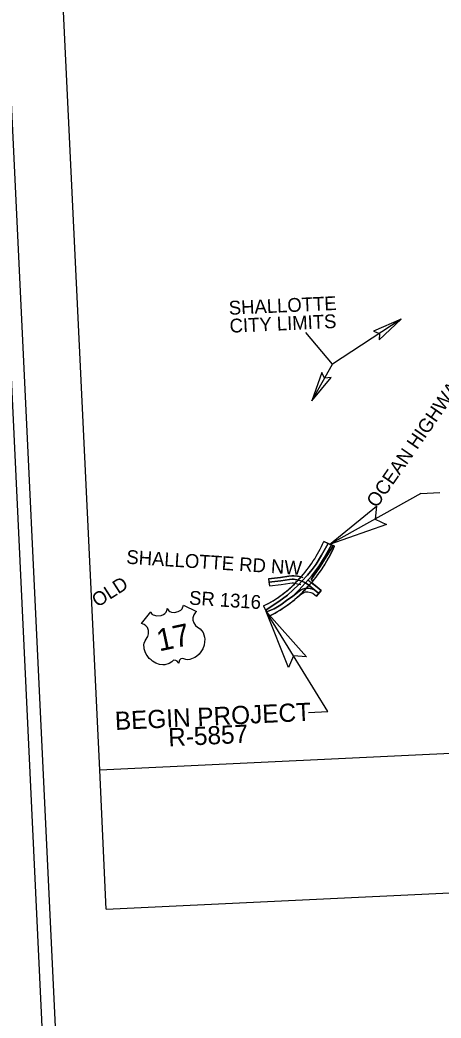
# Model space of a CAD drawing. Extents: x 2170913 to 2188101, y 74009 to 87693.
# Drawn here: x 2172605 to 2173761, y 78286 to 81028 of the extents above; entities that cross this region are included whole.
import ezdxf

# ---------------------------------------------------------------- set-up
doc = ezdxf.new("R2010")
doc.units = 0
for name, color, linetype in [('CTL Primary Horizontal and Vertical Cogo Elevation', 7, 'Continuous'), ('CTL Primary Horizontal Cogo Number', 7, 'Continuous'), ('Exist Other Culture Fence Line', 7, 'Continuous'), ('Exist Right of Way Monument CELL', 7, 'Continuous'), ('Exist Structure Minor Pipes RCP 15 Inch', 7, 'Continuous'), ('Exist Structure Minor Storm Sewer Manhole CELL', 7, 'Continuous'), ('Exist Utilities Water Fire Hydrant CELL', 7, 'Continuous')]:
    doc.layers.add(name, color=color, linetype=linetype)

msp = doc.modelspace()

# ---------------------------------------------------------------- linework, layer by layer
at = {"layer": 'CTL Primary Horizontal and Vertical Cogo Elevation'}
for p, q in [((2173651.6, 80206.1), (2173463, 80082.7)), ((2173463, 80082.7), (2173389.4, 80169.4)), ((2173406, 79981.3), (2173463, 80082.7)), ((2173705.6, 79727.3), (2173454.5, 79587.1)), ((2173705.6, 79727.3), (2173757.7, 79729.7)), ((2173449.6, 79128.3), (2173280.8, 79402.9)), ((2173396.8, 79125.7), (2173449.6, 79128.3)), ((2172841.7, 78585.3), (2172823.6, 78966.9)), ((2172841.7, 78585.3), (2175789.7, 78725.5))]:
    msp.add_line(p, q, dxfattribs=at)
msp.add_lwpolyline([(2172704.4, 81472.7), (2175652.3, 81612.9), (2175771.5, 79107.1), (2172823.6, 78966.9)], close=True, dxfattribs=at)
at = {"layer": 'CTL Primary Horizontal Cogo Number'}
for p, q in [((2172850.9, 74374.1), (2172499.4, 81766.8)), ((2172823.4, 75716.6), (2172535.6, 81768.5))]:
    msp.add_line(p, q, dxfattribs=at)
at = {"layer": 'Exist Other Culture Fence Line'}
msp.add_lwpolyline([(2172938, 79370.1), (2172963.9, 79401.6), (2172967.1, 79395.9), (2172969.9, 79393.8), (2172980, 79390.8), (2172991.9, 79392.1), (2172998.4, 79394.7), (2173002.5, 79397.5), (2173005.6, 79400.6), (2173008.8, 79408.5), (2173008.5, 79411.1), (2173013.1, 79404.3), (2173015.9, 79402.5), (2173021.1, 79400.8), (2173028.8, 79400.2), (2173039.3, 79402.5), (2173046.2, 79406.2), (2173050.2, 79410.1), (2173053.2, 79420.6), (2173089.6, 79402.4), (2173085.3, 79398.7), (2173081.7, 79393.5), (2173079.3, 79385), (2173079.4, 79379.1), (2173081.6, 79371.3), (2173086.3, 79364.3), (2173091.9, 79359.6), (2173099.3, 79354.9), (2173103.4, 79350.7), (2173107.3, 79344.8), (2173111.3, 79332.6), (2173111.9, 79327), (2173111.7, 79319.5), (2173110.1, 79310.2), (2173106.3, 79299.9), (2173101.6, 79291.9), (2173096.7, 79285.6), (2173089.6, 79279.1), (2173085.1, 79276.1), (2173071.2, 79270.8), (2173063.9, 79270.3), (2173060, 79270.7), (2173054.1, 79272.4), (2173051.9, 79273.2), (2173046.5, 79272.3), (2173042.9, 79268.7), (2173041.5, 79266.3), (2173040.4, 79260.7), (2173036.2, 79266), (2173032.9, 79268), (2173026.5, 79268.7), (2173022, 79264.5), (2173014.4, 79259.6), (2173002, 79256.3), (2172996.5, 79256.3), (2172987.6, 79257.6), (2172977.7, 79261), (2172968.5, 79266.5), (2172964.6, 79269.6), (2172959.8, 79274), (2172953.6, 79281.8), (2172951.5, 79285.2), (2172948.2, 79292.1), (2172946, 79299.9), (2172945.4, 79303.2), (2172944.3, 79310.9), (2172946, 79315.6), (2172948, 79322), (2172954.1, 79331.5), (2172955.7, 79334.5), (2172957.6, 79341), (2172957.3, 79350.8), (2172954.5, 79358.5), (2172950.6, 79363.5), (2172945.5, 79367.5), (2172938.5, 79370), (2172938, 79370.1), (2172963.9, 79401.6)], dxfattribs=at)
at = {"layer": 'Exist Right of Way Monument CELL'}
for p, q in [((2173450.5, 79590), (2173432.6, 79557.6)), ((2173450.5, 79590), (2173438.7, 79595.1)), ((2173455.4, 79587.9), (2173450.5, 79590)), ((2173459.6, 79586.1), (2173455.9, 79587.7)), ((2173464.9, 79583.8), (2173459.6, 79586.1)), ((2173462.9, 79580.1), (2173464.9, 79583.8)), ((2173468.1, 79582.4), (2173464.9, 79583.8)), ((2173432.6, 79557.6), (2173417.4, 79532.8)), ((2173427.3, 79523.4), (2173462.9, 79580.1)), ((2173405.4, 79500.1), (2173388.7, 79481.3)), ((2173404.5, 79490.8), (2173427.3, 79523.4)), ((2173287.2, 79492.9), (2173289.4, 79473.1)), ((2173287.2, 79492.9), (2173288.3, 79483)), ((2173288.3, 79483), (2173289.4, 79473.1)), ((2173388.7, 79481.3), (2173378.3, 79486.5)), ((2173378.3, 79486.5), (2173388.7, 79481.3)), ((2173388.7, 79481.3), (2173398.1, 79474.7)), ((2173398.1, 79474.7), (2173398.3, 79474.5)), ((2173413.9, 79461.4), (2173398.3, 79474.5)), ((2173398.3, 79474.5), (2173413.9, 79461.4)), ((2173408.9, 79486.6), (2173404.5, 79490.8)), ((2173404.5, 79490.8), (2173408.9, 79486.6)), ((2173315.4, 79429.8), (2173339.3, 79448.1)), ((2173371.3, 79462.4), (2173352.8, 79444.3)), ((2173413.9, 79461.4), (2173406, 79465)), ((2173408.6, 79452.8), (2173418.8, 79444.7)), ((2173431.3, 79460.3), (2173418.8, 79444.7)), ((2173418.8, 79444.7), (2173425.2, 79452.7)), ((2173425.2, 79452.7), (2173431.3, 79460.3)), ((2173273.5, 79418.3), (2173279.5, 79405.8)), ((2173320.9, 79421.3), (2173340.4, 79436)), ((2173340.4, 79436), (2173352.8, 79444.3)), ((2173279.5, 79405.8), (2173281.1, 79402.5)), ((2173281.1, 79402.5), (2173281.6, 79402)), ((2173281.6, 79402), (2173286, 79403.5)), ((2173281.6, 79402), (2173291.1, 79391.3))]:
    msp.add_line(p, q, dxfattribs=at)
for points in [[(2173378.3, 79486.5), (2173394.1, 79502.2), (2173406.6, 79517.9), (2173417.4, 79532.8), (2173432.6, 79557.6), (2173450.5, 79590)], [(2173388.7, 79481.3), (2173405.4, 79500.1), (2173425.2, 79526.7), (2173440.2, 79550.5), (2173459.6, 79586.1)], [(2173464.9, 79583.8), (2173462.9, 79580.1), (2173427.3, 79523.4), (2173404.5, 79490.8)], [(2173459.6, 79586.1), (2173440.2, 79550.5), (2173425.2, 79526.7), (2173405.4, 79500.1)], [(2173455.9, 79587.7), (2173454.5, 79587.1), (2173455.4, 79587.9)], [(2173417.4, 79532.8), (2173406.6, 79517.9), (2173394.1, 79502.2), (2173378.3, 79486.5)], [(2173287.2, 79492.9), (2173319.6, 79496.6), (2173343, 79500.2), (2173350.8, 79501.2), (2173356.7, 79501.2), (2173366.5, 79499.8), (2173375.5, 79497.6), (2173380.9, 79496.2)], [(2173375.9, 79497.5), (2173375.5, 79497.6), (2173366.5, 79499.8), (2173356.7, 79501.2), (2173350.8, 79501.2), (2173343, 79500.2), (2173319.6, 79496.6), (2173287.2, 79492.9)], [(2173378.3, 79486.5), (2173369, 79475.7), (2173355, 79462.1), (2173339.3, 79448.1), (2173315.4, 79429.8), (2173291.8, 79414.3), (2173280, 79406.2), (2173279.5, 79405.8)], [(2173368.3, 79489.1), (2173364.6, 79489.9), (2173356, 79491.2), (2173351.5, 79491.2), (2173344.4, 79490.3), (2173320.9, 79486.7), (2173288.3, 79483)], [(2173288.3, 79483), (2173320.9, 79486.7), (2173344.4, 79490.3)], [(2173289.4, 79473.1), (2173322.2, 79476.8), (2173345.8, 79480.4), (2173352.2, 79481.2), (2173355.2, 79481.2), (2173362.7, 79480.1), (2173370.6, 79478.2), (2173375.7, 79476.8)], [(2173289.4, 79473.1), (2173322.2, 79476.8), (2173345.8, 79480.4), (2173352.2, 79481.2), (2173355.2, 79481.2), (2173360.2, 79480.5)], [(2173339.3, 79448.1), (2173355, 79462.1), (2173369, 79475.7), (2173378.3, 79486.5)], [(2173344.4, 79490.3), (2173351.5, 79491.2), (2173356, 79491.2)], [(2173352.8, 79444.3), (2173371.3, 79462.4), (2173378.2, 79470.5), (2173388.7, 79481.3)], [(2173356, 79491.2), (2173364.6, 79489.9), (2173368.3, 79489.1)], [(2173378.3, 79486.5), (2173373, 79487.9), (2173368.3, 79489.1)], [(2173368.3, 79489.1), (2173373, 79487.9), (2173378.3, 79486.5)], [(2173388.7, 79481.3), (2173378.2, 79470.5), (2173371.3, 79462.4)], [(2173398.3, 79474.5), (2173398.1, 79474.7), (2173388.7, 79481.3)], [(2173394.5, 79489.5), (2173404.2, 79482.6), (2173420.2, 79469.2), (2173431.3, 79460.3)], [(2173431.3, 79460.3), (2173420.2, 79469.2), (2173404.9, 79482)], [(2173391.2, 79466.7), (2173386.5, 79466.4), (2173380.2, 79464.2), (2173374.4, 79461.1), (2173367.9, 79456.1), (2173352.8, 79444.3)], [(2173352.8, 79444.3), (2173367.9, 79456.1), (2173374.4, 79461.1), (2173380.2, 79464.2), (2173386.5, 79466.4), (2173391.2, 79466.7)], [(2173358.9, 79436.4), (2173374.1, 79448.2), (2173379.8, 79452.6), (2173384.2, 79455), (2173388.5, 79456.5), (2173391.7, 79456.7), (2173395.3, 79456.7), (2173403, 79455.3), (2173408.6, 79452.8)], [(2173366.5, 79442.3), (2173374.1, 79448.2), (2173379.8, 79452.6), (2173384.2, 79455), (2173388.5, 79456.5), (2173391.7, 79456.7), (2173395.3, 79456.7), (2173403, 79455.3), (2173408.6, 79452.8)], [(2173391.3, 79466.7), (2173391.2, 79466.7)], [(2173391.3, 79466.8), (2173391.3, 79466.7)], [(2173391.3, 79466.7), (2173396.2, 79466.7), (2173406, 79465), (2173413.9, 79461.4)], [(2173406, 79465), (2173396.2, 79466.7), (2173391.3, 79466.7)], [(2173408.6, 79452.8), (2173418.8, 79444.7)], [(2173425.2, 79452.7), (2173424.2, 79453.2), (2173413.9, 79461.4)], [(2173413.9, 79461.4), (2173424.2, 79453.2), (2173425.2, 79452.7)], [(2173279.5, 79405.8), (2173280, 79406.2), (2173291.8, 79414.3), (2173315.4, 79429.8)], [(2173352.8, 79444.3), (2173340.4, 79436), (2173320.9, 79421.3), (2173302.6, 79410.4), (2173286, 79403.5), (2173281.6, 79402)], [(2173286, 79403.5), (2173302.6, 79410.4), (2173320.9, 79421.3)]]:
    msp.add_lwpolyline(points, dxfattribs=at)
for centre, radius, start, end in [((2173115.2, 79734.2), 352.2, 316.9455, 336.7273), ((2173115.2, 79734.2), 384.2, 319.863, 336.7273), ((2173137.8, 79698.9), 311.7, 295.8066, 317.689), ((2173137.8, 79698.9), 311.7, 315.5213, 317.689), ((2173137.8, 79698.9), 311.7, 317.689, 318.853), ((2173137.8, 79698.9), 311.7, 317.689, 318.853), ((2173115.2, 79734.2), 352.2, 316.9455, 317.7671), ((2173137.8, 79698.9), 343.7, 317.5106, 318.764), ((2173137.8, 79698.9), 343.7, 317.5195, 318.764), ((2173115.2, 79734.2), 384.2, 317.0247, 317.4668), ((2173115.2, 79734.2), 384.2, 317.0247, 317.4668), ((2173115.2, 79734.2), 384.2, 317.4668, 319.863), ((2173115.2, 79734.2), 384.2, 317.4668, 318.959), ((2173137.8, 79698.9), 343.7, 296.4879, 317.5106), ((2173137.8, 79698.9), 343.7, 311.7052, 317.5106)]:
    msp.add_arc(centre, radius, start, end, dxfattribs=at)
at = {"layer": 'Exist Structure Minor Storm Sewer Manhole CELL'}
for points in [[(2173591.1, 80149.5), (2173651.6, 80206.1), (2173575, 80173.1), (2173591.7, 80166.7)], [(2173433.6, 80059.4), (2173406, 79981.3), (2173458.7, 80045.8), (2173441, 80043.8)], [(2173610.8, 79641.9), (2173454.5, 79587.1), (2173583.8, 79692.3), (2173579.7, 79656.8)], [(2173342.1, 79249), (2173280.8, 79402.9), (2173391.3, 79278.1), (2173355.6, 79280.7)]]:
    msp.add_lwpolyline(points, close=True, dxfattribs=at)
at = {"layer": 'Exist Utilities Water Fire Hydrant CELL'}
for p, q in [((2173438.7, 79595.1), (2173468.1, 79582.4)), ((2173273.5, 79418.3), (2173287.4, 79389.5))]:
    msp.add_line(p, q, dxfattribs=at)
for centre, radius, start, end in [((2173115.2, 79734.2), 352.2, 316.9455, 336.7273), ((2173115.2, 79734.2), 384.2, 317.0247, 336.7273), ((2173137.8, 79698.9), 311.7, 295.8066, 318.853), ((2173137.8, 79698.9), 343.7, 295.8066, 318.764)]:
    msp.add_arc(centre, radius, start, end, dxfattribs=at)

# ---------------------------------------------------------------- texts
at = {"layer": 'CTL Primary Horizontal and Vertical Cogo Elevation'}
for s, p in [('BEGIN PROJECT', (2172866.4, 79077.1)), ('R-5857', (2173012.9, 79031.9))]:
    msp.add_text(s, height=50, rotation=2.723, dxfattribs=at).set_placement(p)
at = {"layer": 'Exist Right of Way Monument CELL'}
msp.add_text('17', height=60.75, rotation=11.9787, dxfattribs=at).set_placement((2172986.9, 79292.9))
at = {"layer": 'Exist Structure Minor Pipes RCP 15 Inch'}
for s, rotation, p in [('SHALLOTTE', 2.5875, (2173178.8, 80218)), ('CITY LIMITS', 2.5875, (2173181, 80168.6)), ('OCEAN HIGHWAY W', 55.3425, (2173584.2, 79685.4)), ('SHALLOTTE RD NW', 356.2981, (2172895.9, 79534.2)), ('OLD', 32.6863, (2172817.5, 79413)), ('SR 1316', 356.2981, (2173068, 79422))]:
    msp.add_text(s, height=37.96, rotation=rotation, dxfattribs=at).set_placement(p)

doc.saveas('drawing.dxf')
